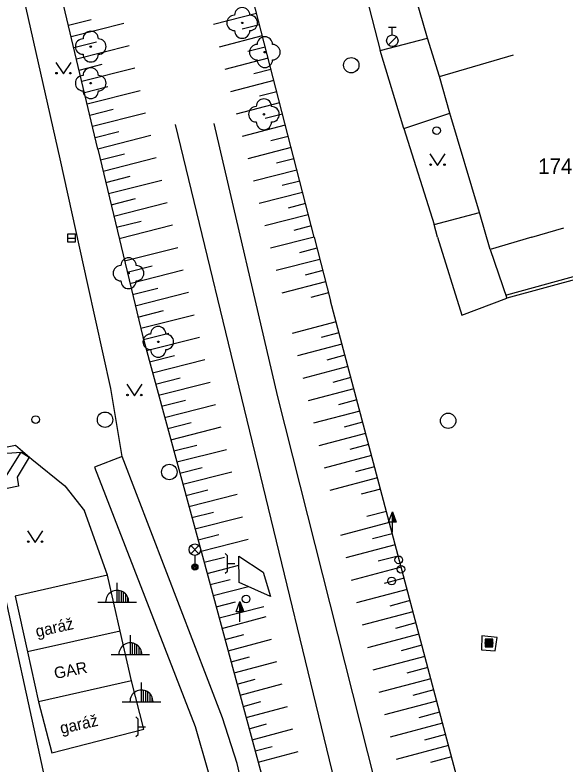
# Model space of a CAD drawing. Extents: x -539515 to -538098, y -1182060 to -1180157.
# Drawn here: x -539031.49 to -538995.73, y -1180534.25 to -1180485.57 of the extents above; entities that cross this region are included whole.
import ezdxf

# ---------------------------------------------------------------- set-up
doc = ezdxf.new("R2010")
doc.units = 0
for name, color, linetype in [('Vrstva 1', 7, 'Continuous'), ('Vrstva 11', 7, 'Continuous'), ('Vrstva 13', 7, 'Continuous'), ('Vrstva 22', 7, 'Continuous'), ('Vrstva 25', 7, 'Continuous'), ('Vrstva 27', 7, 'Continuous'), ('Vrstva 28', 7, 'Continuous'), ('Vrstva 29', 7, 'Continuous'), ('Vrstva 31', 7, 'Continuous'), ('Vrstva 33', 7, 'Continuous'), ('Vrstva 36', 7, 'Continuous'), ('Vrstva 37', 7, 'Continuous'), ('Vrstva 41', 7, 'Continuous'), ('Vrstva 47', 7, 'Continuous'), ('Vrstva 68', 7, 'Continuous'), ('Vrstva 88', 7, 'Continuous')]:
    doc.layers.add(name, color=color, linetype=linetype)

msp = doc.modelspace()

# ---------------------------------------------------------------- linework, layer by layer
at = {"layer": 'Vrstva 1'}
for p, q in [((-539004.67, -1180487.07), (-539006.48, -1180480.75)), ((-539003.89, -1180489.56), (-539004.67, -1180487.07)), ((-539003.89, -1180489.56), (-538999.091, -1180488.156)), ((-539003.23, -1180491.95), (-539003.89, -1180489.56)), ((-539001.3, -1180498.4), (-539003.23, -1180491.95)), ((-539000.6, -1180500.8), (-539001.3, -1180498.4)), ((-538997.88, -1180500), (-538995.801, -1180499.391)), ((-538997.88, -1180500), (-539000.6, -1180500.8)), ((-539025.48, -1180521.97), (-539031.48, -1180523.34)), ((-539024.65, -1180525.62), (-539025.48, -1180521.97)), ((-539031.48, -1180523.34), (-539030.685, -1180526.961)), ((-539024.65, -1180525.62), (-539030.685, -1180526.961)), ((-539023.91, -1180528.85), (-539024.65, -1180525.62)), ((-539030.685, -1180526.961), (-539029.961, -1180530.203)), ((-539023.91, -1180528.85), (-539029.961, -1180530.203)), ((-539023.12, -1180531.98), (-539023.91, -1180528.85)), ((-539029.961, -1180530.203), (-539029.1, -1180533.52)), ((-539029.1, -1180533.52), (-539023.12, -1180531.98))]:
    msp.add_line(p, q, dxfattribs=at)
at = {"layer": 'Vrstva 11'}
msp.add_line((-539000.6, -1180500.8), (-538999.51, -1180503.98), dxfattribs=at)
at = {"layer": 'Vrstva 13'}
for p, q in [((-539007.75, -1180487.88), (-539004.67, -1180487.07)), ((-539006.21, -1180492.95), (-539003.23, -1180491.95)), ((-539004.24, -1180499.18), (-539001.3, -1180498.4)), ((-539032.11, -1180515.609), (-539031.1, -1180513.97)), ((-539030.57, -1180514.3), (-539031.36, -1180515.6)), ((-539024.53, -1180514.26), (-539026.32, -1180514.96)), ((-539018.01, -1180531.25), (-539024.53, -1180514.26)), ((-539026.32, -1180514.96), (-539019.77, -1180531.81)), ((-539031.36, -1180515.6), (-539031.27, -1180516.19)), ((-539031.27, -1180516.19), (-539033.618, -1180516.663))]:
    msp.add_line(p, q, dxfattribs=at)
for points in [[(-539015.35, -1180521.79), (-539014.87, -1180523.35), (-539016.92, -1180522.45), (-539016.94, -1180520.75), (-539015.35, -1180521.79)], [(-539016.35, -1180537.24), (-539017.05, -1180534.22), (-539018.01, -1180531.25)], [(-539019.77, -1180531.81), (-539018.94, -1180534.75), (-539018.1, -1180537.63)]]:
    msp.add_lwpolyline(points, dxfattribs=at)
at = {"layer": 'Vrstva 22'}
for centre in [(-539016.72, -1180486.08), (-539026.57, -1180487.62), (-539015.25, -1180487.98), (-539026.57, -1180490), (-539015.31, -1180492.02), (-539024.11, -1180502.35), (-539022.18, -1180506.81)]:
    msp.add_circle(centre, 0.05, dxfattribs=at)
for centre, start, end in [((-539016.72, -1180485.58), 0, 180), ((-539017.22, -1180486.08), 90, 270), ((-539016.22, -1180486.08), 270, 90), ((-539026.57, -1180487.12), 0, 180), ((-539016.72, -1180486.58), 180, 0), ((-539027.07, -1180487.62), 90, 270), ((-539026.07, -1180487.62), 270, 90), ((-539015.25, -1180487.48), 0, 180), ((-539015.75, -1180487.98), 90, 270), ((-539014.75, -1180487.98), 270, 90), ((-539026.57, -1180488.12), 180, 0), ((-539015.25, -1180488.48), 180, 0), ((-539026.57, -1180489.5), 0, 180), ((-539027.07, -1180490), 90, 270), ((-539026.07, -1180490), 270, 90), ((-539026.57, -1180490.5), 180, 0), ((-539015.31, -1180491.52), 0, 180), ((-539015.81, -1180492.02), 90, 270), ((-539014.81, -1180492.02), 270, 90), ((-539015.31, -1180492.52), 180, 0), ((-539024.11, -1180501.85), 0, 180), ((-539024.61, -1180502.35), 90, 270), ((-539023.61, -1180502.35), 270, 90), ((-539024.11, -1180502.85), 180, 0), ((-539022.18, -1180506.31), 0, 180), ((-539022.68, -1180506.81), 90, 270), ((-539021.68, -1180506.81), 270, 90), ((-539022.18, -1180507.31), 180, 0)]:
    msp.add_arc(centre, 0.5, start, end, dxfattribs=at)
at = {"layer": 'Vrstva 25'}
for p, q in [((-539007.203, -1180518.528), (-539006.95, -1180517.854)), ((-539006.95, -1180518.528), (-539007.203, -1180518.528)), ((-539006.95, -1180519.18), (-539006.95, -1180518.53)), ((-539017.123, -1180524.358), (-539016.87, -1180523.684)), ((-539016.87, -1180524.358), (-539017.123, -1180524.358)), ((-539016.87, -1180525.01), (-539016.87, -1180524.36))]:
    msp.add_line(p, q, dxfattribs=at)
for points in [[(-539006.7, -1180518.53), (-539006.95, -1180518.53), (-539006.95, -1180517.854), (-539006.95, -1180517.854)], [(-539006.758, -1180518.49), (-539006.911, -1180518.49), (-539006.911, -1180518.078)], [(-539006.815, -1180518.451), (-539006.871, -1180518.451), (-539006.871, -1180518.301)], [(-539016.62, -1180524.36), (-539016.87, -1180524.36), (-539016.87, -1180523.684), (-539016.87, -1180523.684)], [(-539016.678, -1180524.32), (-539016.831, -1180524.32), (-539016.831, -1180523.908)], [(-539016.735, -1180524.281), (-539016.791, -1180524.281), (-539016.791, -1180524.131)], [(-539000.916, -1180526.625), (-539000.416, -1180526.625), (-539000.416, -1180526.125), (-539000.916, -1180526.125)], [(-539000.866, -1180526.575), (-539000.466, -1180526.575), (-539000.466, -1180526.175), (-539000.866, -1180526.175)], [(-539000.816, -1180526.525), (-539000.516, -1180526.525), (-539000.516, -1180526.225), (-539000.816, -1180526.225)], [(-539000.766, -1180526.475), (-539000.566, -1180526.475), (-539000.566, -1180526.275), (-539000.766, -1180526.275)], [(-539000.716, -1180526.425), (-539000.616, -1180526.425), (-539000.616, -1180526.325), (-539000.716, -1180526.325)]]:
    msp.add_lwpolyline(points, close=True, dxfattribs=at)
for radius in [0.25, 0.2, 0.15, 0.1, 0.05]:
    msp.add_circle((-539000.666, -1180526.375), radius, dxfattribs=at)
at = {"layer": 'Vrstva 27'}
for p, q in [((-539015.787, -1180485.473), (-539018.583, -1180486.193)), ((-539028.017, -1180486.229), (-539026.546, -1180485.856)), ((-539027.844, -1180486.958), (-539024.411, -1180486.088)), ((-539015.6, -1180486.2), (-539016.719, -1180486.488)), ((-539015.413, -1180486.926), (-539018.213, -1180487.647)), ((-539027.671, -1180487.688), (-539026.185, -1180487.312)), ((-539027.498, -1180488.418), (-539024.06, -1180487.546)), ((-539015.226, -1180487.652), (-539016.347, -1180487.941)), ((-539015.039, -1180488.379), (-539017.843, -1180489.1)), ((-539027.326, -1180489.148), (-539025.823, -1180488.767)), ((-539027.153, -1180489.878), (-539023.709, -1180489.005)), ((-539014.852, -1180489.105), (-539015.974, -1180489.394)), ((-539014.665, -1180489.831), (-539017.473, -1180490.554)), ((-539026.98, -1180490.608), (-539025.462, -1180490.223)), ((-539026.807, -1180491.338), (-539023.358, -1180490.463)), ((-539014.478, -1180490.558), (-539015.602, -1180490.847)), ((-539014.291, -1180491.284), (-539017.103, -1180492.008)), ((-539026.634, -1180492.068), (-539025.1, -1180491.679)), ((-539026.461, -1180492.798), (-539023.008, -1180491.922)), ((-539014.104, -1180492.01), (-539015.23, -1180492.3)), ((-539013.917, -1180492.737), (-539016.733, -1180493.461)), ((-539026.288, -1180493.527), (-539024.739, -1180493.135)), ((-539026.115, -1180494.257), (-539022.657, -1180493.381)), ((-539013.73, -1180493.463), (-539014.857, -1180493.753)), ((-539013.543, -1180494.189), (-539016.363, -1180494.915)), ((-539025.941, -1180494.987), (-539024.377, -1180494.591)), ((-539025.766, -1180495.716), (-539022.306, -1180494.839)), ((-539013.356, -1180494.916), (-539014.485, -1180495.206)), ((-539013.17, -1180495.642), (-539015.993, -1180496.369)), ((-539025.592, -1180496.446), (-539024.016, -1180496.046)), ((-539025.417, -1180497.175), (-539021.955, -1180496.298)), ((-539012.983, -1180496.368), (-539014.113, -1180496.659)), ((-539012.796, -1180497.095), (-539015.623, -1180497.822)), ((-539025.242, -1180497.905), (-539023.654, -1180497.502)), ((-539025.068, -1180498.634), (-539021.605, -1180497.756)), ((-539012.609, -1180497.821), (-539013.74, -1180498.112)), ((-539012.422, -1180498.547), (-539015.252, -1180499.276)), ((-539024.893, -1180499.364), (-539023.293, -1180498.958)), ((-539024.719, -1180500.093), (-539021.254, -1180499.215)), ((-539012.235, -1180499.274), (-539013.368, -1180499.565)), ((-539028.07, -1180500.07), (-539027.57, -1180500.07)), ((-539012.048, -1180500), (-539014.882, -1180500.729)), ((-539024.369, -1180501.552), (-539020.903, -1180500.673)), ((-539011.861, -1180500.726), (-539012.995, -1180501.018)), ((-539011.674, -1180501.453), (-539014.512, -1180502.183)), ((-539024.195, -1180502.282), (-539022.57, -1180501.87)), ((-539024.02, -1180503.011), (-539020.552, -1180502.132)), ((-539011.487, -1180502.179), (-539012.623, -1180502.471)), ((-539011.3, -1180502.905), (-539014.142, -1180503.637)), ((-539023.846, -1180503.741), (-539022.208, -1180503.325)), ((-539023.671, -1180504.47), (-539020.202, -1180503.59)), ((-539011.113, -1180503.632), (-539012.251, -1180503.924)), ((-539023.496, -1180505.199), (-539021.847, -1180504.781)), ((-539023.322, -1180505.929), (-539019.851, -1180505.049)), ((-539010.619, -1180505.507), (-539013.482, -1180506.267)), ((-539023.142, -1180506.657), (-539021.485, -1180506.237)), ((-539022.945, -1180507.381), (-539019.5, -1180506.507)), ((-539010.427, -1180506.232), (-539011.579, -1180506.537)), ((-539010.235, -1180506.957), (-539013.132, -1180507.725)), ((-539022.747, -1180508.105), (-539021.124, -1180507.693)), ((-539022.55, -1180508.828), (-539019.149, -1180507.966)), ((-539010.042, -1180507.682), (-539011.208, -1180507.991)), ((-539009.85, -1180508.406), (-539012.782, -1180509.185)), ((-539022.353, -1180509.552), (-539020.762, -1180509.149)), ((-539022.156, -1180510.276), (-539018.798, -1180509.424)), ((-539009.658, -1180509.131), (-539010.837, -1180509.444)), ((-539009.465, -1180509.856), (-539012.432, -1180510.643)), ((-539021.959, -1180511), (-539020.401, -1180510.604)), ((-539021.762, -1180511.723), (-539018.448, -1180510.883)), ((-539009.273, -1180510.581), (-539010.467, -1180510.898)), ((-539009.08, -1180511.306), (-539012.082, -1180512.102)), ((-539021.564, -1180512.447), (-539020.039, -1180512.06)), ((-539021.367, -1180513.171), (-539018.097, -1180512.342)), ((-539008.888, -1180512.031), (-539010.096, -1180512.351)), ((-539008.696, -1180512.756), (-539011.732, -1180513.562)), ((-539021.17, -1180513.895), (-539019.678, -1180513.516)), ((-539020.973, -1180514.618), (-539017.746, -1180513.8)), ((-539008.503, -1180513.481), (-539009.725, -1180513.805)), ((-539008.311, -1180514.206), (-539011.382, -1180515.02)), ((-539020.776, -1180515.342), (-539019.316, -1180514.972)), ((-539020.579, -1180516.066), (-539017.395, -1180515.259)), ((-539008.119, -1180514.931), (-539009.354, -1180515.258)), ((-539007.926, -1180515.656), (-539011.032, -1180516.48)), ((-539020.382, -1180516.79), (-539018.955, -1180516.428)), ((-539020.184, -1180517.513), (-539017.045, -1180516.717)), ((-539007.734, -1180516.38), (-539008.983, -1180516.712)), ((-539019.987, -1180518.237), (-539018.593, -1180517.883)), ((-539019.79, -1180518.961), (-539016.694, -1180518.176)), ((-539007.349, -1180517.83), (-539008.612, -1180518.166)), ((-539007.157, -1180518.555), (-539010.332, -1180519.397)), ((-539019.593, -1180519.685), (-539018.232, -1180519.339)), ((-539019.396, -1180520.408), (-539016.343, -1180519.634)), ((-539006.964, -1180519.28), (-539008.241, -1180519.619)), ((-539006.772, -1180520.005), (-539009.981, -1180520.857)), ((-539017.82, -1180520.568), (-539017.678, -1180520.71)), ((-539017.678, -1180521.71), (-539017.678, -1180520.71)), ((-539019.199, -1180521.132), (-539017.871, -1180520.795)), ((-539006.58, -1180520.73), (-539007.87, -1180521.072)), ((-539019.003, -1180521.856), (-539016.933, -1180521.331)), ((-539017.678, -1180521.21), (-539017.19, -1180521.21)), ((-539006.387, -1180521.455), (-539009.631, -1180522.316)), ((-539017.82, -1180521.85), (-539017.678, -1180521.71)), ((-539006.195, -1180522.18), (-539007.5, -1180522.526)), ((-539018.807, -1180522.58), (-539017.512, -1180522.252)), ((-539018.611, -1180523.304), (-539016.306, -1180522.72)), ((-539006.003, -1180522.905), (-539009.281, -1180523.774)), ((-539005.81, -1180523.63), (-539007.129, -1180523.979)), ((-539018.416, -1180524.029), (-539017.153, -1180523.708)), ((-539018.22, -1180524.753), (-539015.309, -1180524.014)), ((-539005.618, -1180524.354), (-539008.931, -1180525.234)), ((-539018.035, -1180525.435), (-539015.156, -1180524.663)), ((-539005.426, -1180525.079), (-539006.758, -1180525.433)), ((-539017.839, -1180526.16), (-539016.621, -1180525.833)), ((-539005.233, -1180525.804), (-539008.581, -1180526.693)), ((-539017.644, -1180526.883), (-539014.811, -1180526.124)), ((-539005.041, -1180526.529), (-539006.387, -1180526.886)), ((-539017.448, -1180527.607), (-539016.25, -1180527.287)), ((-539004.848, -1180527.254), (-539008.224, -1180528.15)), ((-539017.252, -1180528.332), (-539014.467, -1180527.585)), ((-539004.656, -1180527.979), (-539006.008, -1180528.338)), ((-539017.056, -1180529.055), (-539015.879, -1180528.74)), ((-539004.464, -1180528.704), (-539007.847, -1180529.602)), ((-539016.86, -1180529.78), (-539014.123, -1180529.046)), ((-539004.271, -1180529.429), (-539005.626, -1180529.788)), ((-539016.665, -1180530.503), (-539015.509, -1180530.194)), ((-539004.079, -1180530.154), (-539007.47, -1180531.053)), ((-539016.469, -1180531.228), (-539013.778, -1180530.506)), ((-539003.887, -1180530.879), (-539005.245, -1180531.239)), ((-539023.63, -1180531.188), (-539023.488, -1180531.33)), ((-539023.488, -1180532.33), (-539023.488, -1180531.33)), ((-539023.488, -1180531.83), (-539023, -1180531.83)), ((-539016.273, -1180531.952), (-539015.138, -1180531.647)), ((-539003.694, -1180531.604), (-539007.093, -1180532.506)), ((-539023.63, -1180532.47), (-539023.488, -1180532.33)), ((-539016.077, -1180532.675), (-539013.434, -1180531.967)), ((-539003.502, -1180532.328), (-539004.863, -1180532.69)), ((-539015.881, -1180533.4), (-539014.767, -1180533.101)), ((-539003.309, -1180533.053), (-539006.716, -1180533.958)), ((-539015.686, -1180534.123), (-539013.089, -1180533.428)), ((-539003.117, -1180533.778), (-539004.481, -1180534.14))]:
    msp.add_line(p, q, dxfattribs=at)
msp.add_lwpolyline([(-539028.07, -1180500.32), (-539027.57, -1180500.32), (-539027.57, -1180499.82), (-539028.07, -1180499.82)], close=True, dxfattribs=at)
for centre in [(-539009.63, -1180488.83), (-539025.64, -1180511.87), (-539003.33, -1180511.94), (-539021.46, -1180515.27)]:
    msp.add_circle(centre, 0.5, dxfattribs=at)
at = {"layer": 'Vrstva 28'}
for p, q in [((-539007.21, -1180486.364), (-539006.71, -1180486.364)), ((-539006.96, -1180486.864), (-539006.96, -1180486.364)), ((-539007.219, -1180487.511), (-539006.689, -1180486.981))]:
    msp.add_line(p, q, dxfattribs=at)
msp.add_circle((-539006.96, -1180487.24), 0.375, dxfattribs=at)
at = {"layer": 'Vrstva 29'}
for p, q in [((-539012.048, -1180500), (-539018.51, -1180474.89)), ((-539026.11, -1180494.28), (-539030.48, -1180475.83)), ((-539021.08, -1180492.68), (-539010.09, -1180538.02)), ((-539018.57, -1180492.62), (-539014.42, -1180510.38)), ((-539026.11, -1180494.28), (-539023.19, -1180506.48)), ((-539012.048, -1180500), (-539010.98, -1180504.15)), ((-539002.54, -1180535.95), (-539010.98, -1180504.15)), ((-539023.19, -1180506.48), (-539019.24, -1180520.98)), ((-539014.42, -1180510.38), (-539003.89, -1180552.06)), ((-539019.24, -1180520.98), (-539014.87, -1180537.14))]:
    msp.add_line(p, q, dxfattribs=at)
at = {"layer": 'Vrstva 31'}
for centre in [(-539004.08, -1180493.08), (-539030.15, -1180511.86), (-539006.54, -1180520.98), (-539006.4, -1180521.59), (-539007, -1180522.35), (-539016.47, -1180523.52)]:
    msp.add_circle(centre, 0.25, dxfattribs=at)
at = {"layer": 'Vrstva 33'}
for p, q in [((-539020.064, -1180520.581), (-539019.536, -1180520.051)), ((-539020.064, -1180520.051), (-539019.536, -1180520.581)), ((-539019.8, -1180520.69), (-539019.8, -1180521.44))]:
    msp.add_line(p, q, dxfattribs=at)
for centre, radius in [((-539019.8, -1180520.316), 0.375), ((-539019.8, -1180521.441), 0.2), ((-539019.8, -1180521.441), 0.145), ((-539019.8, -1180521.441), 0.0876)]:
    msp.add_circle(centre, radius, dxfattribs=at)
at = {"layer": 'Vrstva 36'}
for points in [[(-539028.846, -1180488.648), (-539028.346, -1180489.398), (-539027.846, -1180488.648)], [(-539004.517, -1180494.594), (-539004.017, -1180495.344), (-539003.517, -1180494.594)], [(-539024.231, -1180509.57), (-539023.731, -1180510.32), (-539023.231, -1180509.57)], [(-539030.683, -1180519.094), (-539030.183, -1180519.844), (-539029.683, -1180519.094)]]:
    msp.add_lwpolyline(points, dxfattribs=at)
for centre in [(-539028.796, -1180489.348), (-539027.897, -1180489.348), (-539004.467, -1180495.294), (-539003.568, -1180495.294), (-539024.181, -1180510.27), (-539023.282, -1180510.27), (-539030.633, -1180519.794), (-539029.734, -1180519.794)]:
    msp.add_circle(centre, 0.05, dxfattribs=at)
at = {"layer": 'Vrstva 37'}
for p, q in [((-539024.85, -1180523.72), (-539024.85, -1180522.463)), ((-539024.711, -1180523.72), (-539024.711, -1180522.975)), ((-539024.57, -1180523.72), (-539024.57, -1180523.016)), ((-539024.43, -1180523.72), (-539024.43, -1180523.09)), ((-539024.289, -1180523.72), (-539024.289, -1180523.213)), ((-539024.15, -1180523.72), (-539024.15, -1180523.441)), ((-539026.1, -1180523.72), (-539023.6, -1180523.72)), ((-539023.99, -1180527.13), (-539023.99, -1180525.873)), ((-539023.851, -1180527.13), (-539023.851, -1180526.385)), ((-539023.71, -1180527.13), (-539023.71, -1180526.426)), ((-539023.57, -1180527.13), (-539023.57, -1180526.5)), ((-539023.429, -1180527.13), (-539023.429, -1180526.623)), ((-539023.29, -1180527.13), (-539023.29, -1180526.851)), ((-539025.24, -1180527.13), (-539022.74, -1180527.13)), ((-539023.27, -1180530.2), (-539023.27, -1180528.943)), ((-539023.131, -1180530.2), (-539023.131, -1180529.455)), ((-539022.99, -1180530.2), (-539022.99, -1180529.496)), ((-539022.85, -1180530.2), (-539022.85, -1180529.57)), ((-539022.709, -1180530.2), (-539022.709, -1180529.693)), ((-539022.57, -1180530.2), (-539022.57, -1180529.921)), ((-539024.52, -1180530.2), (-539022.02, -1180530.2))]:
    msp.add_line(p, q, dxfattribs=at)
for centre in [(-539024.85, -1180523.712), (-539023.99, -1180527.122), (-539023.27, -1180530.192)]:
    msp.add_arc(centre, 0.75, 359.377, 180.623, dxfattribs=at)
at = {"layer": 'Vrstva 68'}
for p, q in [((-538985.885, -1180500), (-538999.529, -1180503.773)), ((-538985.125, -1180500), (-538999.51, -1180503.98)), ((-538999.566, -1180503.781), (-538999.529, -1180503.773)), ((-538999.51, -1180503.98), (-538999.566, -1180503.781)), ((-539033.618, -1180516.663), (-539029.53, -1180535.34))]:
    msp.add_line(p, q, dxfattribs=at)
at = {"layer": 'Vrstva 88'}
for p, q in [((-539028.56, -1180494.92), (-539033.17, -1180474.42)), ((-539010.82, -1180475.89), (-539007.75, -1180487.88)), ((-539006.21, -1180492.95), (-539007.75, -1180487.88)), ((-539006.21, -1180492.95), (-539004.24, -1180499.18)), ((-539026.76, -1180503.08), (-539028.56, -1180494.92)), ((-539004.02, -1180500), (-539004.24, -1180499.18)), ((-539004.02, -1180500), (-539002.44, -1180505.07)), ((-539025.27, -1180509.84), (-539026.76, -1180503.08)), ((-539002.44, -1180505.07), (-538999.51, -1180503.98)), ((-539024.53, -1180514.26), (-539025.27, -1180509.84)), ((-539034.36, -1180514.2), (-539031.1, -1180513.97)), ((-539031.1, -1180513.97), (-539030.57, -1180514.3)), ((-539028.25, -1180516.16), (-539026.98, -1180517.79)), ((-539025.48, -1180521.97), (-539026.98, -1180517.79)), ((-539001.13, -1180525.92), (-539001.17, -1180526.83)), ((-539000.15, -1180526.02), (-539001.13, -1180525.92)), ((-539000.28, -1180526.89), (-539000.15, -1180526.02)), ((-539001.17, -1180526.83), (-539000.28, -1180526.89))]:
    msp.add_line(p, q, dxfattribs=at)
msp.add_lwpolyline([(-539036.43, -1180514.4), (-539032.43, -1180513.73), (-539031.47, -1180513.52), (-539030.39, -1180514.43), (-539028.25, -1180516.16)], dxfattribs=at)

# ---------------------------------------------------------------- texts
at = {"layer": 'Vrstva 41'}
for s, rotation, p in [('garáž', 12.6, (-539030.067, -1180526.008)), ('GAR', 10.9465, (-539028.876, -1180528.726)), ('garáž', 12.6, (-539028.479, -1180532.297))]:
    msp.add_text(s, height=0.75, rotation=rotation, dxfattribs=at).set_placement(p)
at = {"layer": 'Vrstva 47'}
msp.add_text('1744', height=1, dxfattribs=at).set_placement((-538997.483, -1180495.891))

doc.saveas('drawing.dxf')
